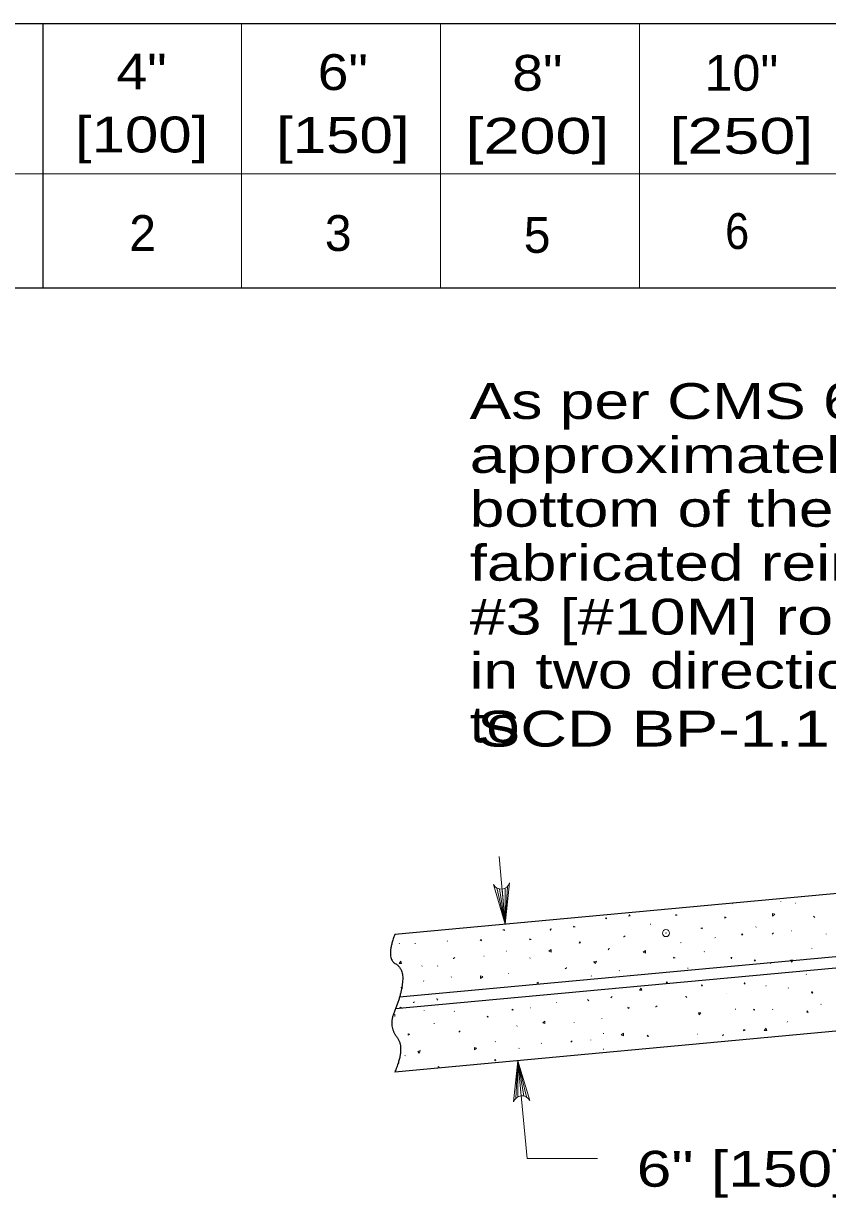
# Model space of a CAD drawing. Extents: x 1083.1 to 1117.1, y 697.4 to 741.4.
# Drawn here: x 1101.68 to 1105.17, y 723.19 to 728.3 of the extents above; entities that cross this region are included whole.
import ezdxf
from ezdxf.enums import TextEntityAlignment as Align

# ---------------------------------------------------------------- set-up
doc = ezdxf.new("R2010")
doc.units = 0
doc.header["$LTSCALE"] = 0.062
doc.header["$PDMODE"] = 32
doc.header["$PDSIZE"] = 0.031
doc.layers.add('1', color=7, linetype='Continuous', lineweight=13)

msp = doc.modelspace()

# ---------------------------------------------------------------- linework, layer by layer
at = {"layer": '1', "lineweight": 25}
for p, q in [((1099.49967, 728.29617), (1107.81608, 728.29617)), ((1101.75875, 728.29617), (1101.75875, 727.14608)), ((1110.5145, 724.72675), (1103.31092, 724.05875)), ((1110.51908, 724.67717), (1103.29317, 724.007)), ((1110.14883, 724.368), (1103.29017, 723.73208))]:
    msp.add_line(p, q, dxfattribs=at)
at = {"layer": '1'}
for p, q in [((1102.62408, 728.29617), (1102.62408, 727.14608)), ((1103.48942, 728.29617), (1103.48942, 727.14608)), ((1104.35475, 728.29617), (1104.35475, 727.14608)), ((1099.49967, 727.6425), (1107.81608, 727.6425)), ((1103.77075, 724.3765), (1103.7435, 724.67092)), ((1103.73367, 724.534), (1103.77075, 724.3765)), ((1103.74517, 724.52958), (1103.77075, 724.3765)), ((1103.75667, 724.529), (1103.77075, 724.3765)), ((1103.77067, 724.53317), (1103.77075, 724.3765)), ((1103.7805, 724.54025), (1103.77075, 724.3765)), ((1104.75983, 724.46392), (1104.76092, 724.46558)), ((1104.96958, 724.47592), (1104.96892, 724.47408)), ((1105.035, 724.46708), (1105.033, 724.46775)), ((1104.40133, 724.376), (1104.40333, 724.37683)), ((1104.86008, 724.36375), (1104.86158, 724.36492)), ((1104.68483, 724.31792), (1104.68283, 724.31725)), ((1105.01617, 724.3465), (1105.01767, 724.34775)), ((1105.16683, 724.33467), (1105.16608, 724.33267)), ((1103.30958, 724.291), (1103.31025, 724.29292)), ((1103.37825, 724.29117), (1103.37908, 724.29308)), ((1103.5195, 724.30292), (1103.51825, 724.30142)), ((1103.77483, 724.25817), (1103.77675, 724.259)), ((1104.53342, 724.29525), (1104.53542, 724.29608)), ((1104.63683, 724.257), (1104.63567, 724.2555)), ((1105.1045, 724.27225), (1105.10375, 724.27033)), ((1103.6775, 724.2365), (1103.6795, 724.23717)), ((1103.87958, 724.2295), (1103.87758, 724.22883)), ((1104.9265, 724.20567), (1104.92575, 724.20383)), ((1103.40725, 724.19333), (1103.40925, 724.19408)), ((1103.47583, 724.19358), (1103.47783, 724.19433)), ((1103.78533, 724.16175), (1103.78417, 724.16025)), ((1104.14567, 724.14942), (1104.145, 724.15133)), ((1104.26767, 724.17425), (1104.26567, 724.1735)), ((1104.56408, 724.184), (1104.566, 724.18475)), ((1105.08092, 724.15883), (1105.08025, 724.15683)), ((1103.41617, 724.12808), (1103.41542, 724.13008)), ((1103.53667, 724.14675), (1103.5355, 724.14525)), ((1104.69125, 724.13742), (1104.692, 724.13942)), ((1104.90483, 724.1085), (1104.904, 724.1065)), ((1105.00117, 724.09783), (1105.00275, 724.09908)), ((1104.73342, 724.07375), (1104.7335, 724.07367)), ((1103.41742, 723.999), (1103.41817, 724.00092)), ((1103.882, 724.01233), (1103.88, 724.0115)), ((1103.9955, 724.03583), (1103.99358, 724.03508)), ((1104.77208, 724.00542), (1104.77283, 724.00742)), ((1104.93342, 724.00367), (1104.93408, 724.00558)), ((1105.14392, 724.02675), (1105.14542, 724.02792)), ((1103.54858, 723.99617), (1103.55058, 723.99683)), ((1104.06975, 723.94758), (1104.07092, 723.94908)), ((1104.19025, 723.96625), (1104.191, 723.96425)), ((1104.99775, 723.95183), (1104.99708, 723.94983)), ((1103.46075, 723.94483), (1103.4615, 723.94283)), ((1103.821, 723.93258), (1103.82225, 723.93408)), ((1104.19917, 723.901), (1104.19725, 723.90017)), ((1104.60858, 723.89767), (1104.60658, 723.897)), ((1103.72675, 723.86467), (1103.72875, 723.8655)), ((1103.92892, 723.85783), (1103.927, 723.857)), ((1104.14308, 723.87333), (1104.14242, 723.87142)), ((1103.33433, 723.80442), (1103.33633, 723.80375)), ((1103.83167, 723.83608), (1103.82967, 723.83533)), ((1104.19908, 723.83233), (1104.19708, 723.8315)), ((1103.81617, 723.618), (1103.82583, 723.78175)), ((1103.84, 723.62925), (1103.82583, 723.78175)), ((1103.82592, 723.62508), (1103.82583, 723.78175)), ((1103.85142, 723.62867), (1103.82583, 723.78175)), ((1103.863, 723.62425), (1103.82583, 723.78175))]:
    msp.add_line(p, q, dxfattribs=at)
at = {"layer": '1', "lineweight": 25}
for points in [[(1099.49967, 728.29617), (1099.49967, 727.14608), (1107.81608, 727.14608)], [(1110.14883, 724.96767), (1107.49917, 724.722), (1103.29017, 724.33175)]]:
    msp.add_lwpolyline(points, dxfattribs=at)
at = {"layer": '1'}
for points in [[(1103.78967, 724.556), (1103.77075, 724.3765), (1103.71917, 724.5495)], [(1104.94325, 724.41917), (1104.93333, 724.41167), (1104.9335, 724.42267), (1104.943, 724.41925)], [(1105.11183, 724.41133), (1105.11242, 724.40992), (1105.11742, 724.40567)], [(1104.28633, 724.31908), (1104.28692, 724.32042), (1104.29192, 724.32467)], [(1104.93733, 724.33817), (1104.93592, 724.3375), (1104.93175, 724.3325)], [(1103.9605, 724.25808), (1103.97025, 724.26558), (1103.97008, 724.25458), (1103.96067, 724.25808)], [(1104.22367, 724.27033), (1104.22225, 724.26975), (1104.21808, 724.26475)], [(1104.37075, 724.25375), (1104.38058, 724.26125), (1104.3805, 724.25025), (1104.371, 724.25367)], [(1103.31617, 724.215), (1103.30875, 724.20517), (1103.31975, 724.20533), (1103.31625, 724.21483)], [(1103.54517, 724.22567), (1103.54575, 724.22708), (1103.55067, 724.23117)], [(1104.15517, 724.21208), (1104.167, 724.21567), (1104.16308, 724.20542), (1104.15542, 724.21192)], [(1105.0155, 724.21017), (1105.02283, 724.22), (1105.012, 724.21983), (1105.01542, 724.21042)], [(1103.67308, 724.14758), (1103.66325, 724.14008), (1103.66342, 724.151), (1103.67292, 724.14767)], [(1104.03717, 724.1875), (1104.0365, 724.18625), (1104.03167, 724.182)], [(1103.47192, 724.05117), (1103.47333, 724.05058), (1103.4775, 724.04558)], [(1104.1345, 724.04308), (1104.13308, 724.04367), (1104.12892, 724.04867)], [(1104.23542, 724.06117), (1104.23483, 724.05983), (1104.22992, 724.05558)], [(1104.36175, 724.09817), (1104.35442, 724.08842), (1104.36525, 724.08858), (1104.36192, 724.098)], [(1104.55567, 724.06217), (1104.55633, 724.06083), (1104.56117, 724.05658)], [(1103.37092, 724.03308), (1103.37158, 724.0345), (1103.37658, 724.03858)], [(1104.42542, 724.0145), (1104.42608, 724.01592), (1104.43108, 724.02008)], [(1103.29017, 723.97442), (1103.29067, 723.974), (1103.29058, 723.985), (1103.29017, 723.98492)], [(1103.93342, 723.94675), (1103.94317, 723.95425), (1103.943, 723.94325), (1103.93358, 723.94667)], [(1104.61408, 723.98083), (1104.6215, 723.99067), (1104.61058, 723.99042), (1104.614, 723.981)], [(1103.56925, 723.90667), (1103.56983, 723.90808), (1103.57483, 723.91225)], [(1104.27525, 723.89442), (1104.285, 723.90175), (1104.28483, 723.89075), (1104.27542, 723.89425)], [(1104.715, 723.89042), (1104.71642, 723.891), (1104.72058, 723.896)], [(1104.90483, 723.92283), (1104.89742, 723.91308), (1104.90833, 723.91317), (1104.90492, 723.92267)], [(1104.06133, 723.86858), (1104.06075, 723.86717), (1104.05575, 723.863)], [(1105.03775, 723.89408), (1105.03525, 723.8945), (1105.03558, 723.89392)], [(1103.39708, 723.814), (1103.40067, 723.82575), (1103.39033, 723.82183), (1103.39683, 723.81417)], [(1103.646, 723.83608), (1103.63625, 723.82875), (1103.63633, 723.83975), (1103.64583, 723.83625)], [(1103.80692, 723.60225), (1103.82583, 723.78175), (1103.87742, 723.60875)], [(1103.82583, 723.78175), (1103.86533, 723.356), (1104.1725, 723.356)]]:
    msp.add_lwpolyline(points, dxfattribs=at)
for points in [[(1104.3115, 724.41792), (1104.3135, 724.41225), (1104.30825, 724.41158)], [(1104.51833, 724.41542), (1104.51283, 724.41342), (1104.512, 724.41867)], [(1104.73142, 724.40458), (1104.72583, 724.40267), (1104.72508, 724.40792)], [(1103.96767, 724.349), (1103.96575, 724.35458), (1103.971, 724.35542)], [(1104.07442, 724.3645), (1104.06883, 724.3625), (1104.06808, 724.36783)], [(1104.20475, 724.4025), (1104.21033, 724.40442), (1104.21117, 724.39917)], [(1104.62108, 724.35875), (1104.62667, 724.36075), (1104.6275, 724.35542)], [(1103.66083, 724.30733), (1103.66642, 724.30933), (1103.66708, 724.30408)], [(1103.76083, 724.35158), (1103.7665, 724.3535), (1103.76725, 724.34825)], [(1103.88342, 724.30942), (1103.87783, 724.30758), (1103.87708, 724.31283)], [(1104.80067, 724.33542), (1104.79867, 724.32983), (1104.80392, 724.32917)], [(1104.09525, 724.30025), (1104.09725, 724.29467), (1104.092, 724.29392)], [(1104.5095, 724.2295), (1104.50392, 724.22758), (1104.50308, 724.23275)], [(1104.75467, 724.22508), (1104.75667, 724.23067), (1104.75142, 724.2315)], [(1104.85558, 724.2225), (1104.85367, 724.21692), (1104.85883, 724.21608)], [(1103.31675, 724.10033), (1103.32225, 724.10225), (1103.32308, 724.09708)], [(1103.90792, 724.12142), (1103.91358, 724.12342), (1103.91433, 724.11825)], [(1104.47417, 724.12633), (1104.47617, 724.12075), (1104.47083, 724.12008)], [(1104.62558, 724.11358), (1104.62358, 724.108), (1104.62875, 724.10717)], [(1104.81142, 724.12233), (1104.80942, 724.11683), (1104.81467, 724.11608)], [(1105.10475, 724.08258), (1105.10283, 724.07708), (1105.108, 724.07625)], [(1103.31925, 724.01342), (1103.31367, 724.01542), (1103.313, 724.01008)], [(1103.80658, 724.00367), (1103.80108, 724.00158), (1103.80025, 724.00692)], [(1104.3105, 724.01175), (1104.30492, 724.00983), (1104.30425, 724.01508)], [(1104.85342, 723.99983), (1104.85542, 724.00542), (1104.85017, 724.00625)], [(1105.08458, 723.99842), (1105.08258, 723.99283), (1105.08783, 723.99217)], [(1103.6985, 723.97275), (1103.69292, 723.97083), (1103.69217, 723.97608)], [(1103.35417, 723.897), (1103.34858, 723.89892), (1103.34775, 723.89367)], [(1104.81383, 723.91558), (1104.80825, 723.91758), (1104.80758, 723.91225)], [(1104.38992, 723.89375), (1104.38783, 723.88817), (1104.39317, 723.8875)], [(1103.48517, 723.75408), (1103.47958, 723.75608), (1103.47892, 723.75075)], [(1103.723, 723.78483), (1103.72858, 723.78675), (1103.72942, 723.78142)]]:
    msp.add_lwpolyline(points, close=True, dxfattribs=at)
for centre, start, end in [((1103.75307, 724.56698), 207.3832, 343.20933), ((1103.84354, 723.59128), 27.38556, 163.21169)]:
    msp.add_arc(centre, 0.0382, start, end, dxfattribs=at)
at = {"layer": '1', "lineweight": 25}
msp.add_open_spline([(1103.29017, 724.33175), (1103.25142, 724.22767), (1103.33125, 724.18283), (1103.31608, 724.06042), (1103.26142, 723.93308), (1103.33625, 723.83808), (1103.29017, 723.73208)], degree=2, dxfattribs=at)
at = {"layer": '1'}
msp.add_point((1104.46975, 724.33742), dxfattribs=at)

# ---------------------------------------------------------------- texts
for s, width, p in [('4"', 1.15, (1102.189, 728.00908)), ('6"', 1.15, (1103.06433, 728.0065)), ('8"', 1.15, (1103.91067, 728.00333)), ('10"', 1.05, (1104.79767, 728.00333)), ('[100]', 1.25, (1102.189, 727.73508)), ('[150]', 1.25, (1103.06433, 727.7325)), ('[200]', 1.35, (1103.91067, 727.72933)), ('[250]', 1.35, (1104.79767, 727.72933))]:
    msp.add_text(s, height=0.156, dxfattribs=dict(at, width=width)).set_placement(p, align=Align.CENTER)
for s, width, p in [('6', 0.9, (1104.72717, 727.31467)), ('As per CMS 601.04.D, reinforce the slab ', 1.3, (1103.61583, 726.575)), ('approximately midway between the top and ', 1.35, (1103.61583, 726.34033)), ('bottom of the slab, with steel bars or ', 1.3, (1103.61583, 726.10567)), ('fabricated reinforcement equivalent to ', 1.3, (1103.61583, 725.871)), ('#3 [#10M] round bars, at 24" [600] o.c.', 1.35, (1103.61583, 725.63633)), ('in two directions, or wire fabric according ', 1.3, (1103.61583, 725.40167)), ('to ', 1.25, (1103.61583, 725.167)), ('    SCD BP-1.1', 1.35, (1103.33525, 725.149)), ('6" [150] Reinforced', 1.3, (1104.3425, 723.2335))]:
    msp.add_text(s, height=0.156, dxfattribs=dict(at, width=width)).set_placement(p)
for s, p in [('2', (1102.13525, 727.30608)), ('3', (1102.98617, 727.30608)), ('5', (1103.85133, 727.298))]:
    msp.add_text(s, height=0.156, dxfattribs=at).set_placement(p)

doc.saveas('drawing.dxf')
